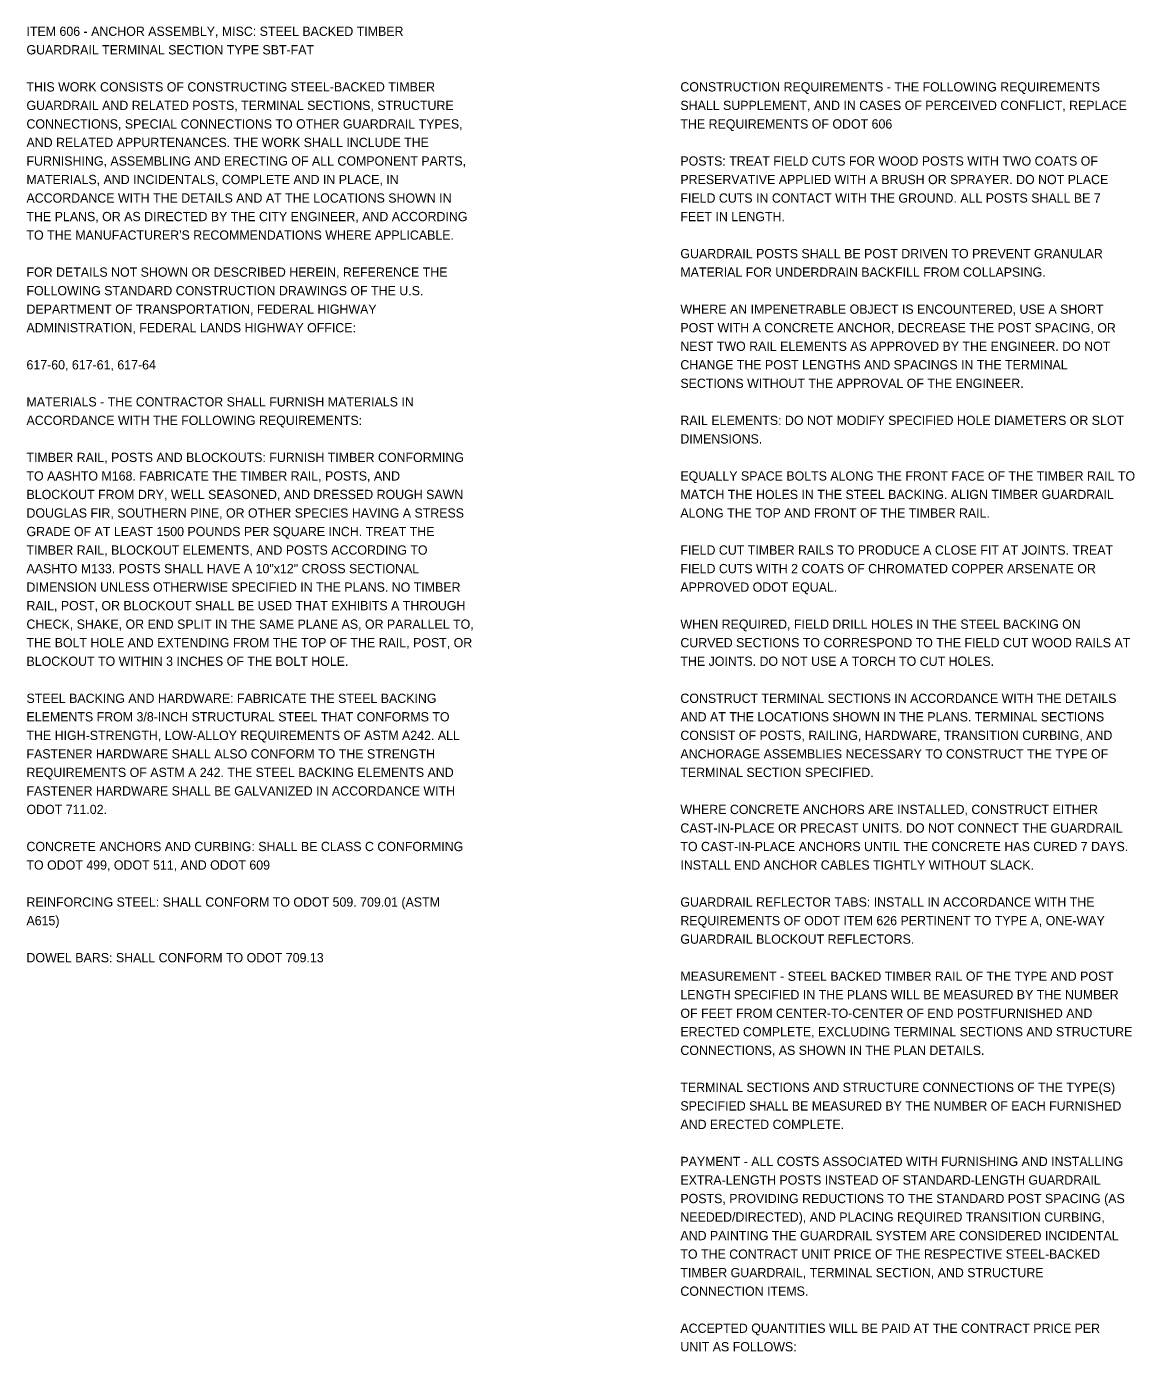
# Model space of a CAD drawing. Extents: x 0 to 84.3, y -13.4 to 22.
# Drawn here: x 42.96 to 59.71, y -13.44 to 6.58 of the extents above; entities that cross this region are included whole.
import ezdxf

# ---------------------------------------------------------------- set-up
doc = ezdxf.new("R2010")
doc.units = 0
doc.layers.add('SH_Text', color=7, linetype='Continuous')

msp = doc.modelspace()

# ---------------------------------------------------------------- texts
at = {"layer": 'SH_Text'}
for s, p in [('ITEM 606 - ANCHOR ASSEMBLY, MISC: STEEL BACKED TIMBER ', (42.957, 6.44)), ('GUARDRAIL TERMINAL SECTION TYPE SBT-FAT', (42.957, 6.16)), ('THIS WORK CONSISTS OF CONSTRUCTING STEEL-BACKED TIMBER ', (42.957, 5.6)), ('CONSTRUCTION REQUIREMENTS - THE FOLLOWING REQUIREMENTS ', (52.845, 5.6)), ('GUARDRAIL AND RELATED POSTS, TERMINAL SECTIONS, STRUCTURE ', (42.957, 5.32)), ('SHALL SUPPLEMENT, AND IN CASES OF PERCEIVED CONFLICT, REPLACE ', (52.845, 5.32)), ('CONNECTIONS, SPECIAL CONNECTIONS TO OTHER GUARDRAIL TYPES, ', (42.957, 5.04)), ('THE REQUIREMENTS OF ODOT 606', (52.845, 5.04)), ('AND RELATED APPURTENANCES. THE WORK SHALL INCLUDE THE ', (42.957, 4.76)), ('FURNISHING, ASSEMBLING AND ERECTING OF ALL COMPONENT PARTS, ', (42.957, 4.48)), ('POSTS: TREAT FIELD CUTS FOR WOOD POSTS WITH TWO COATS OF ', (52.845, 4.48)), ('MATERIALS, AND INCIDENTALS, COMPLETE AND IN PLACE, IN ', (42.957, 4.2)), ('PRESERVATIVE APPLIED WITH A BRUSH OR SPRAYER. DO NOT PLACE ', (52.845, 4.2)), ('ACCORDANCE WITH THE DETAILS AND AT THE LOCATIONS SHOWN IN ', (42.957, 3.92)), ('FIELD CUTS IN CONTACT WITH THE GROUND. ALL POSTS SHALL BE 7 ', (52.845, 3.92)), ('THE PLANS, OR AS DIRECTED BY THE CITY ENGINEER, AND ACCORDING ', (42.957, 3.64)), ('FEET IN LENGTH.', (52.845, 3.64)), ("TO THE MANUFACTURER'S RECOMMENDATIONS WHERE APPLICABLE.", (42.957, 3.36)), ('GUARDRAIL POSTS SHALL BE POST DRIVEN TO PREVENT GRANULAR ', (52.845, 3.08)), ('FOR DETAILS NOT SHOWN OR DESCRIBED HEREIN, REFERENCE THE', (42.957, 2.8)), ('MATERIAL FOR UNDERDRAIN BACKFILL FROM COLLAPSING.', (52.845, 2.8)), ('FOLLOWING STANDARD CONSTRUCTION DRAWINGS OF THE U.S. ', (42.957, 2.52)), ('DEPARTMENT OF TRANSPORTATION, FEDERAL HIGHWAY ', (42.957, 2.24)), ('WHERE AN IMPENETRABLE OBJECT IS ENCOUNTERED, USE A SHORT ', (52.845, 2.24)), ('ADMINISTRATION, FEDERAL LANDS HIGHWAY OFFICE:', (42.957, 1.96)), ('POST WITH A CONCRETE ANCHOR, DECREASE THE POST SPACING, OR ', (52.845, 1.96)), ('NEST TWO RAIL ELEMENTS AS APPROVED BY THE ENGINEER. DO NOT ', (52.845, 1.68)), ('617-60, 617-61, 617-64', (42.957, 1.4)), ('CHANGE THE POST LENGTHS AND SPACINGS IN THE TERMINAL ', (52.845, 1.4)), ('SECTIONS WITHOUT THE APPROVAL OF THE ENGINEER.', (52.845, 1.12)), ('MATERIALS - THE CONTRACTOR SHALL FURNISH MATERIALS IN', (42.957, 0.84)), ('ACCORDANCE WITH THE FOLLOWING REQUIREMENTS:', (42.957, 0.56)), ('RAIL ELEMENTS: DO NOT MODIFY SPECIFIED HOLE DIAMETERS OR SLOT', (52.845, 0.56)), ('DIMENSIONS. ', (52.845, 0.28)), ('TIMBER RAIL, POSTS AND BLOCKOUTS: FURNISH TIMBER CONFORMING ', (42.957, 0)), ('TO AASHTO M168. FABRICATE THE TIMBER RAIL, POSTS, AND ', (42.957, -0.28)), ('EQUALLY SPACE BOLTS ALONG THE FRONT FACE OF THE TIMBER RAIL TO ', (52.845, -0.28)), ('BLOCKOUT FROM DRY, WELL SEASONED, AND DRESSED ROUGH SAWN ', (42.957, -0.56)), ('MATCH THE HOLES IN THE STEEL BACKING. ALIGN TIMBER GUARDRAIL ', (52.845, -0.56)), ('DOUGLAS FIR, SOUTHERN PINE, OR OTHER SPECIES HAVING A STRESS ', (42.957, -0.84)), ('ALONG THE TOP AND FRONT OF THE TIMBER RAIL. ', (52.845, -0.84)), ('GRADE OF AT LEAST 1500 POUNDS PER SQUARE INCH. TREAT THE ', (42.957, -1.12)), ('TIMBER RAIL, BLOCKOUT ELEMENTS, AND POSTS ACCORDING TO ', (42.957, -1.4)), ('FIELD CUT TIMBER RAILS TO PRODUCE A CLOSE FIT AT JOINTS. TREAT ', (52.845, -1.4)), ('AASHTO M133. POSTS SHALL HAVE A 10"x12" CROSS SECTIONAL ', (42.957, -1.68)), ('FIELD CUTS WITH 2 COATS OF CHROMATED COPPER ARSENATE OR ', (52.845, -1.68)), ('DIMENSION UNLESS OTHERWISE SPECIFIED IN THE PLANS. NO TIMBER ', (42.957, -1.96)), ('APPROVED ODOT EQUAL.', (52.845, -1.96)), ('RAIL, POST, OR BLOCKOUT SHALL BE USED THAT EXHIBITS A THROUGH ', (42.957, -2.24)), ('CHECK, SHAKE, OR END SPLIT IN THE SAME PLANE AS, OR PARALLEL TO, ', (42.957, -2.52)), ('WHEN REQUIRED, FIELD DRILL HOLES IN THE STEEL BACKING ON ', (52.845, -2.52)), ('THE BOLT HOLE AND EXTENDING FROM THE TOP OF THE RAIL, POST, OR ', (42.957, -2.8)), ('CURVED SECTIONS TO CORRESPOND TO THE FIELD CUT WOOD RAILS AT ', (52.845, -2.8)), ('BLOCKOUT TO WITHIN 3 INCHES OF THE BOLT HOLE.', (42.957, -3.08)), ('THE JOINTS. DO NOT USE A TORCH TO CUT HOLES. ', (52.845, -3.08)), ('STEEL BACKING AND HARDWARE: FABRICATE THE STEEL BACKING ', (42.957, -3.64)), ('CONSTRUCT TERMINAL SECTIONS IN ACCORDANCE WITH THE DETAILS ', (52.845, -3.64)), ('ELEMENTS FROM 3/8-INCH STRUCTURAL STEEL THAT CONFORMS TO ', (42.957, -3.92)), ('AND AT THE LOCATIONS SHOWN IN THE PLANS. TERMINAL SECTIONS ', (52.845, -3.92)), ('THE HIGH-STRENGTH, LOW-ALLOY REQUIREMENTS OF ASTM A242. ALL ', (42.957, -4.2)), ('CONSIST OF POSTS, RAILING, HARDWARE, TRANSITION CURBING, AND ', (52.845, -4.2)), ('FASTENER HARDWARE SHALL ALSO CONFORM TO THE STRENGTH ', (42.957, -4.48)), ('ANCHORAGE ASSEMBLIES NECESSARY TO CONSTRUCT THE TYPE OF ', (52.845, -4.48)), ('REQUIREMENTS OF ASTM A 242. THE STEEL BACKING ELEMENTS AND ', (42.957, -4.76)), ('TERMINAL SECTION SPECIFIED. ', (52.845, -4.76)), ('FASTENER HARDWARE SHALL BE GALVANIZED IN ACCORDANCE WITH ', (42.957, -5.04)), ('ODOT 711.02.', (42.957, -5.32)), ('WHERE CONCRETE ANCHORS ARE INSTALLED, CONSTRUCT EITHER ', (52.845, -5.32)), ('CAST-IN-PLACE OR PRECAST UNITS. DO NOT CONNECT THE GUARDRAIL ', (52.845, -5.6)), ('CONCRETE ANCHORS AND CURBING: SHALL BE CLASS C CONFORMING ', (42.957, -5.88)), ('TO CAST-IN-PLACE ANCHORS UNTIL THE CONCRETE HAS CURED 7 DAYS. ', (52.845, -5.88)), ('TO ODOT 499, ODOT 511, AND ODOT 609', (42.957, -6.16)), ('INSTALL END ANCHOR CABLES TIGHTLY WITHOUT SLACK. ', (52.845, -6.16)), ('REINFORCING STEEL: SHALL CONFORM TO ODOT 509. 709.01 (ASTM ', (42.957, -6.72)), ('GUARDRAIL REFLECTOR TABS: INSTALL IN ACCORDANCE WITH THE ', (52.845, -6.72)), ('A615)', (42.957, -7)), ('REQUIREMENTS OF ODOT ITEM 626 PERTINENT TO TYPE A, ONE-WAY ', (52.845, -7)), ('GUARDRAIL BLOCKOUT REFLECTORS. ', (52.845, -7.28)), ('DOWEL BARS: SHALL CONFORM TO ODOT 709.13', (42.957, -7.56)), ('MEASUREMENT - STEEL BACKED TIMBER RAIL OF THE TYPE AND POST ', (52.845, -7.84)), ('LENGTH SPECIFIED IN THE PLANS WILL BE MEASURED BY THE NUMBER ', (52.845, -8.12)), ('OF FEET FROM CENTER-TO-CENTER OF END POSTFURNISHED AND ', (52.845, -8.4)), ('ERECTED COMPLETE, EXCLUDING TERMINAL SECTIONS AND STRUCTURE ', (52.845, -8.68)), ('CONNECTIONS, AS SHOWN IN THE PLAN DETAILS.', (52.845, -8.96)), ('TERMINAL SECTIONS AND STRUCTURE CONNECTIONS OF THE TYPE(S) ', (52.845, -9.52)), ('SPECIFIED SHALL BE MEASURED BY THE NUMBER OF EACH FURNISHED ', (52.845, -9.8)), ('AND ERECTED COMPLETE.', (52.845, -10.08)), ('PAYMENT - ALL COSTS ASSOCIATED WITH FURNISHING AND INSTALLING ', (52.845, -10.64)), ('EXTRA-LENGTH POSTS INSTEAD OF STANDARD-LENGTH GUARDRAIL ', (52.845, -10.92)), ('POSTS, PROVIDING REDUCTIONS TO THE STANDARD POST SPACING (AS  ', (52.845, -11.2)), ('NEEDED/DIRECTED), AND PLACING REQUIRED TRANSITION CURBING, ', (52.845, -11.48)), ('AND PAINTING THE GUARDRAIL SYSTEM ARE CONSIDERED INCIDENTAL ', (52.845, -11.76)), ('TO THE CONTRACT UNIT PRICE OF THE RESPECTIVE STEEL-BACKED ', (52.845, -12.04)), ('TIMBER GUARDRAIL, TERMINAL SECTION, AND STRUCTURE ', (52.845, -12.32)), ('CONNECTION ITEMS. ', (52.845, -12.6)), ('ACCEPTED QUANTITIES WILL BE PAID AT THE CONTRACT PRICE PER ', (52.845, -13.16)), ('UNIT AS FOLLOWS:', (52.845, -13.44))]:
    msp.add_text(s, height=0.14, dxfattribs=at).set_placement(p)

doc.saveas('drawing.dxf')
